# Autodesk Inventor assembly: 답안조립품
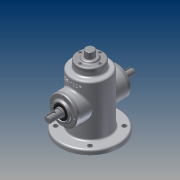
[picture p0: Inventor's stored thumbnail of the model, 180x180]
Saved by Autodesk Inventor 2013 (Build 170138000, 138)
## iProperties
Created: 2014-12
Part Number: 답안조립품
Document SubType Name: Assembly
Designer: HS002
Author: HS002
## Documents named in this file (12)
- C:\Users\HS002\Desktop\441228V1007\답안조립품.iam
- C:\Users\HS002\Desktop\441228V1007\본체.ipt
- C:\Users\HS002\Desktop\441228V1007\M3x0.5x8.ipt
- M3x0.5.ipt
- C:\Users\HS002\Desktop\441228V1007\베어링 6002.ipt
- 베어링 6002.ipt
- C:\Users\HS002\Desktop\441228V1007\상단커버.ipt
- C:\Users\HS002\Desktop\441228V1007\슬라이드.ipt
- C:\Users\HS002\Desktop\441228V1007\오일실.ipt
- 오일실.ipt
- C:\Users\HS002\Desktop\441228V1007\커버.ipt
- C:\Users\HS002\Desktop\441228V1007\편심축.ipt
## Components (12 placed, 1 different names)
1. M3x0.5:1 — 각도:6
2. M3x0.5:2 — 각도:4
3. M3x0.5:3 — 각도:2
4. M3x0.5:4 — 각도:3
5. M3x0.5:5 — 각도:11
6. M3x0.5:6 — 각도:10
7. M3x0.5:7 — 각도:9
8. M3x0.5:8 — 각도:7
9. M3x0.5:9 — 각도:5
10. M3x0.5:10 — 각도:12
11. M3x0.5:11 — 각도:8
12. M3x0.5:12 — 각도:1
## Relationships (12: Angle 12)
- 각도:1 [Angle]: M3x0.5:12
- 각도:2 [Angle]: M3x0.5:3
- 각도:3 [Angle]: M3x0.5:4
- 각도:4 [Angle]: M3x0.5:2
- 각도:5 [Angle]: M3x0.5:9
- 각도:6 [Angle]: M3x0.5:1
- 각도:7 [Angle]: M3x0.5:8
- 각도:8 [Angle]: M3x0.5:11
- 각도:9 [Angle]: M3x0.5:7
- 각도:10 [Angle]: M3x0.5:6
- 각도:11 [Angle]: M3x0.5:5
- 각도:12 [Angle]: M3x0.5:10
